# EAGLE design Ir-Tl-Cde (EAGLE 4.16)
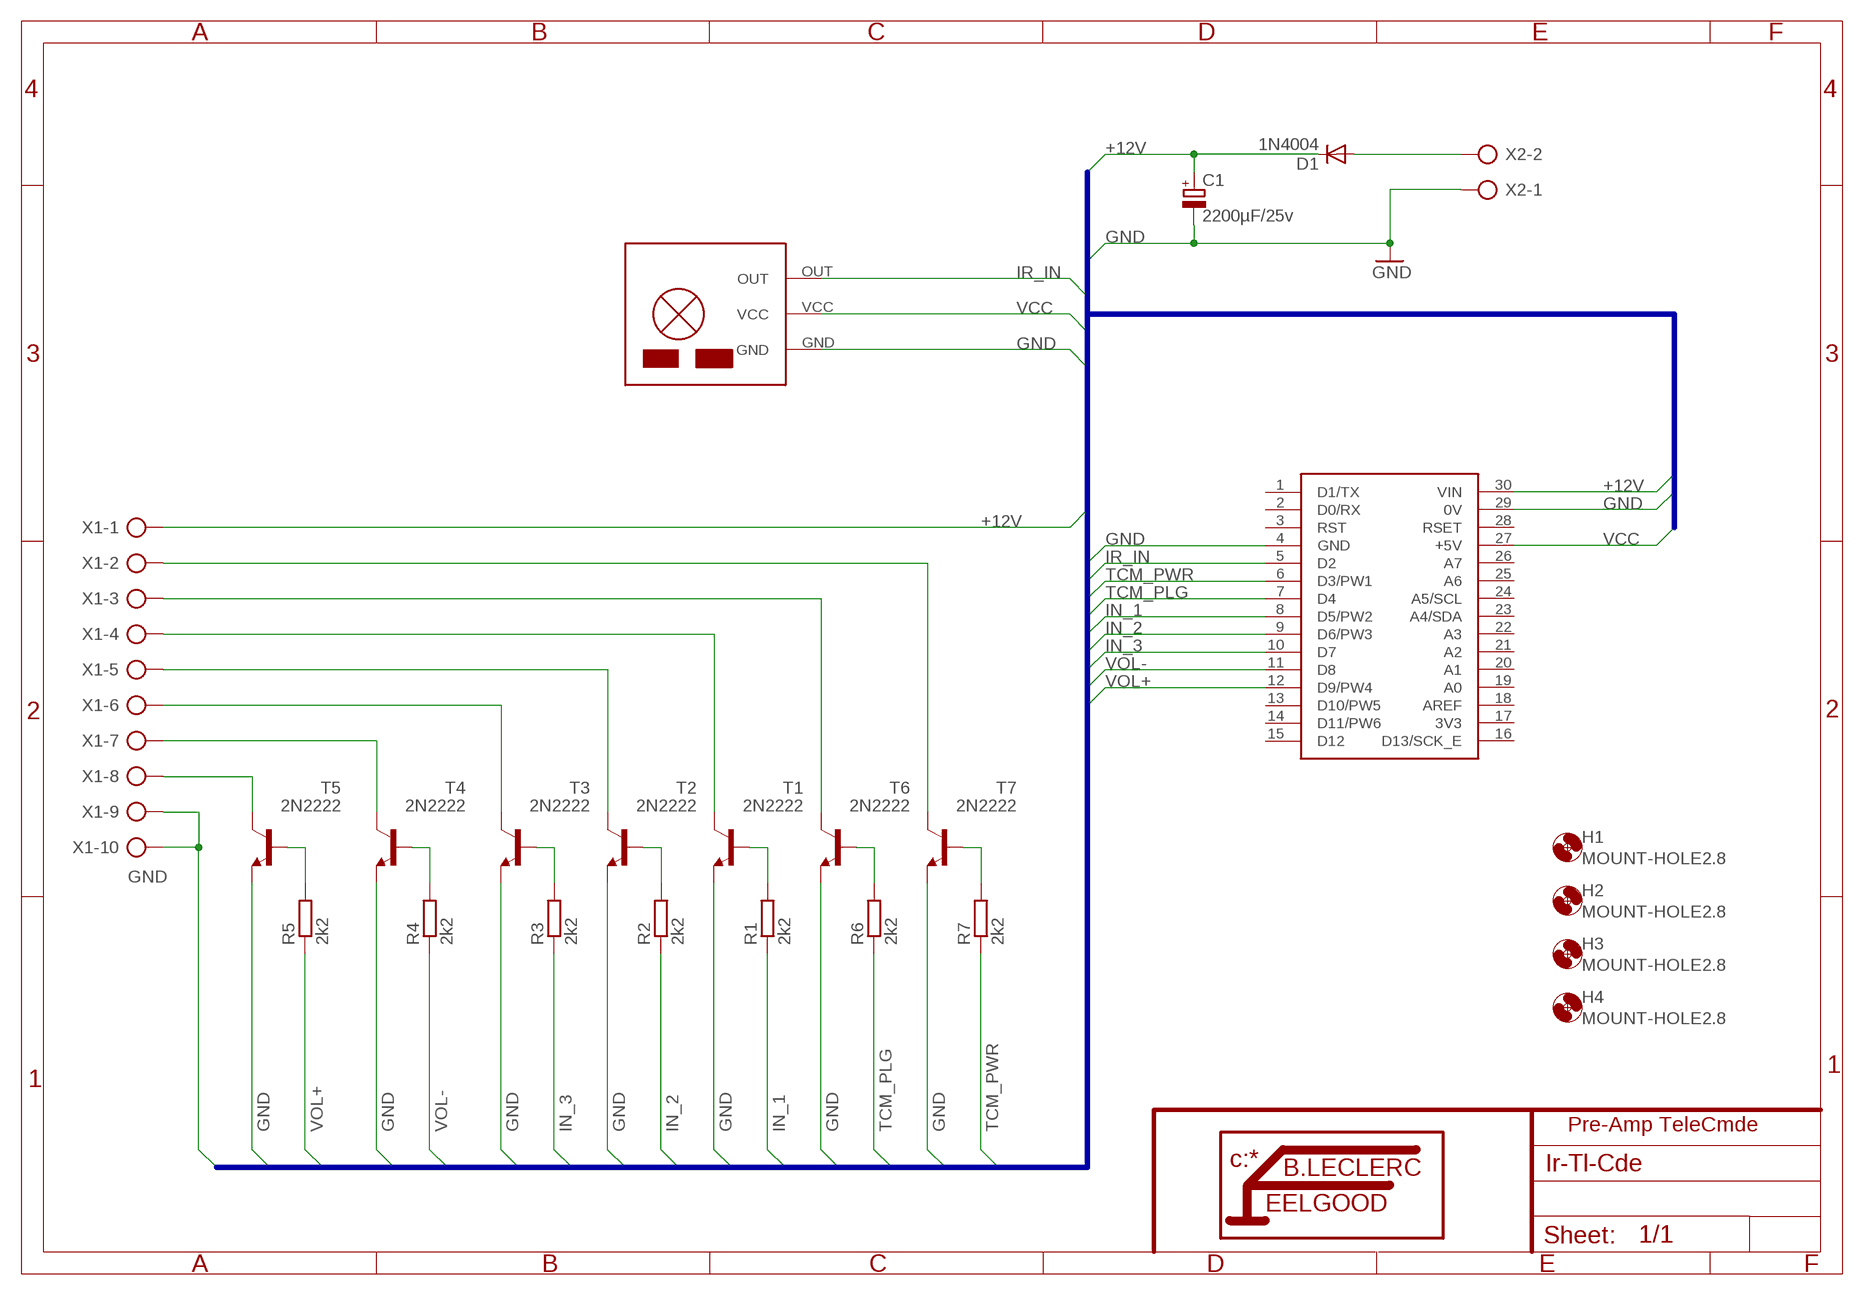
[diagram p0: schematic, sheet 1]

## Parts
C1  2200µF/25v  CPOL-EUE7.5-16  [E7,5-16]
D1  1N4004  [DO41-10]
H1  MOUNT-HOLE2.8  [2,8]
H2  MOUNT-HOLE2.8  [2,8]
H3  MOUNT-HOLE2.8  [2,8]
H4  MOUNT-HOLE2.8  [2,8]
IR1  KEYES_PCB  [KEYES_PCB]
R1  2k2  R-EU_0207/10  [0207/10]
R2  2k2  R-EU_0207/10  [0207/10]
R3  2k2  R-EU_0207/10  [0207/10]
R4  2k2  R-EU_0207/10  [0207/10]
R5  2k2  R-EU_0207/10  [0207/10]
R6  2k2  R-EU_0207/10  [0207/10]
R7  2k2  R-EU_0207/10  [0207/10]
T1  2N2222  [TO18]
T2  2N2222  [TO18]
T3  2N2222  [TO18]
T4  2N2222  [TO18]
T5  2N2222  [TO18]
T6  2N2222  [TO18]
T7  2N2222  [TO18]
U1  NANO  [NANO]
X1  AK300/10  [AK300/10]
X2  AK300/2  [AK300/2]

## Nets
+12V: C1.+ D1.C U1.30(VIN) X1.1
GND: C1.- IR1.GND T1.1(E) T2.1(E) T3.1(E) T4.1(E) T5.1(E) T6.1(E) T7.1(E) U1.4(GND) U1.29(0V) X1.9 X1.10 X2.1
IN_1: R1.1 U1.8(D5/PW2)
IN_2: R2.1 U1.9(D6/PW3)
IN_3: R3.1 U1.10(D7)
IR_IN: IR1.OUT U1.5(D2)
N$1: T5.3(C) X1.8
N$2: T4.3(C) X1.7
N$3: T3.3(C) X1.6
N$4: T2.3(C) X1.5
N$5: T1.3(C) X1.4
N$6: R5.2 T5.2(B)
N$7: R4.2 T4.2(B)
N$8: R3.2 T3.2(B)
N$9: R2.2 T2.2(B)
N$10: R1.2 T1.2(B)
N$11: D1.A X2.2
N$40: R6.2 T6.2(B)
N$59: R7.2 T7.2(B)
N$69: T6.3(C) X1.3
N$74: T7.3(C) X1.2
TCM_PLG: R6.1 U1.7(D4)
TCM_PWR: R7.1 U1.6(D3/PW1)
VCC: IR1.VCC U1.27(+5V)
VOL+: R5.1 U1.12(D9/PW4)
VOL-: R4.1 U1.11(D8)
Unconnected: U1.1(D1/TX) U1.2(D0/RX) U1.3(RST) U1.13(D10/PW5) U1.14(D11/PW6) U1.15(D12) U1.16(D13/SCK_E) U1.18(AREF) U1.19(A0) U1.20(A1) U1.21(A2) U1.22(A3) U1.23(A4/SDA) U1.24(A5/SCL) U1.25(A6) U1.26(A7) U1.28(RSET)

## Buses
B$1

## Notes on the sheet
- Pre-Amp TeleCmde

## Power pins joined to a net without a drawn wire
3V3: U1.17(3V3)

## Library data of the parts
C1 = rcl:CPOL-EU: POLARIZED CAPACITOR, European symbol
D1 = diode:1N4004: DIODE
H1-H4 = holes:MOUNT-HOLE: MOUNTING HOLE with drill center marker
IR1 = opto-vishay:KEYES_PCB
R1-R7 = rcl:R-EU_: RESISTOR, European symbol
T1-T7 = transistor:2N2222: NPN TRANSISTOR
U1 = Arduino:NANO
X1 = con-ptr500:AK300/10: CONNECTOR
X2 = con-ptr500:AK300/2: CONNECTOR

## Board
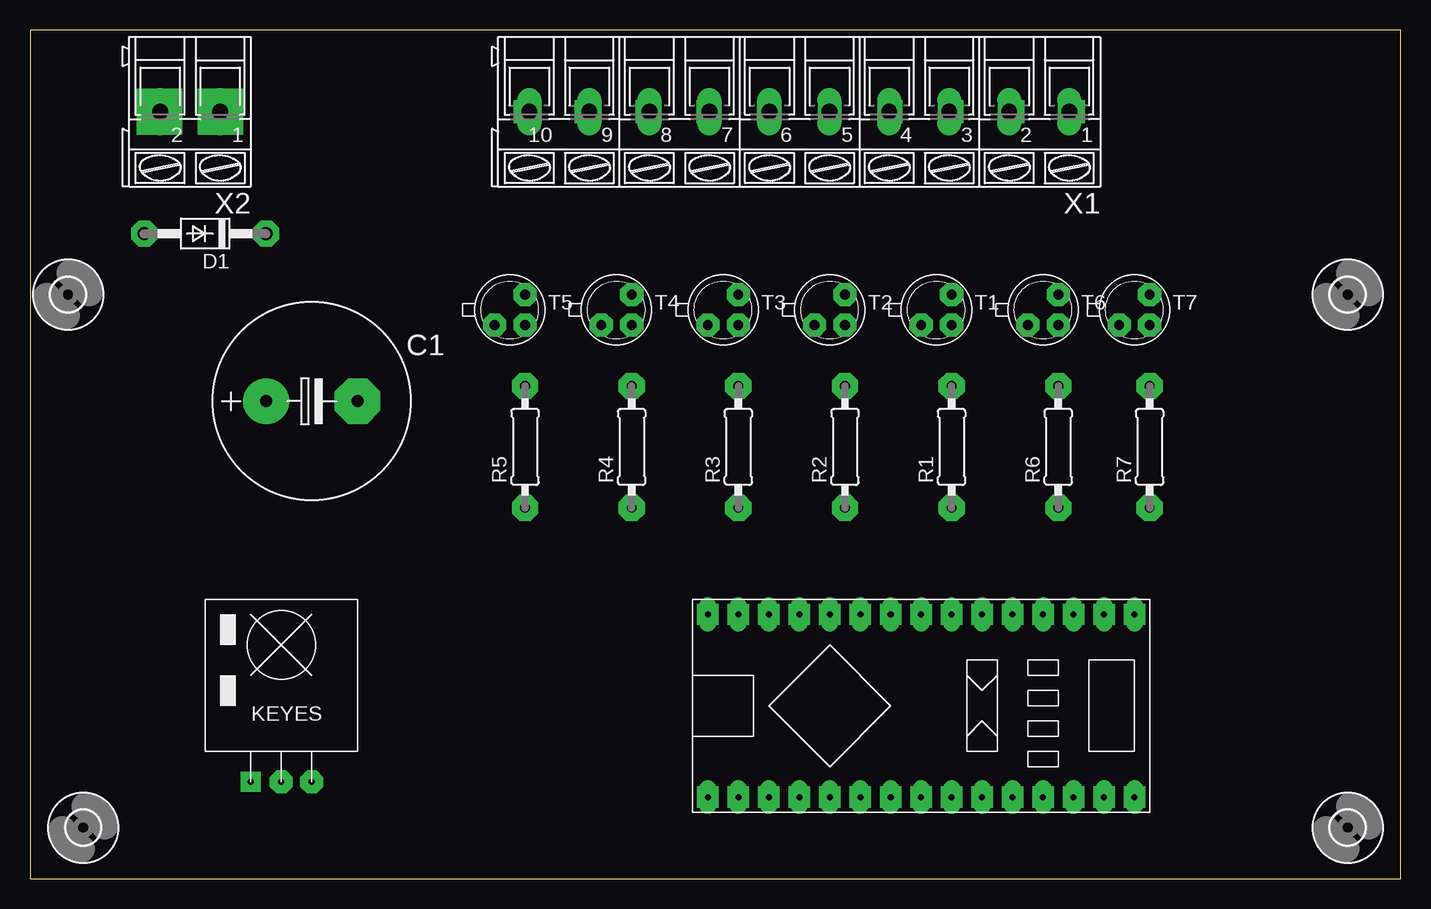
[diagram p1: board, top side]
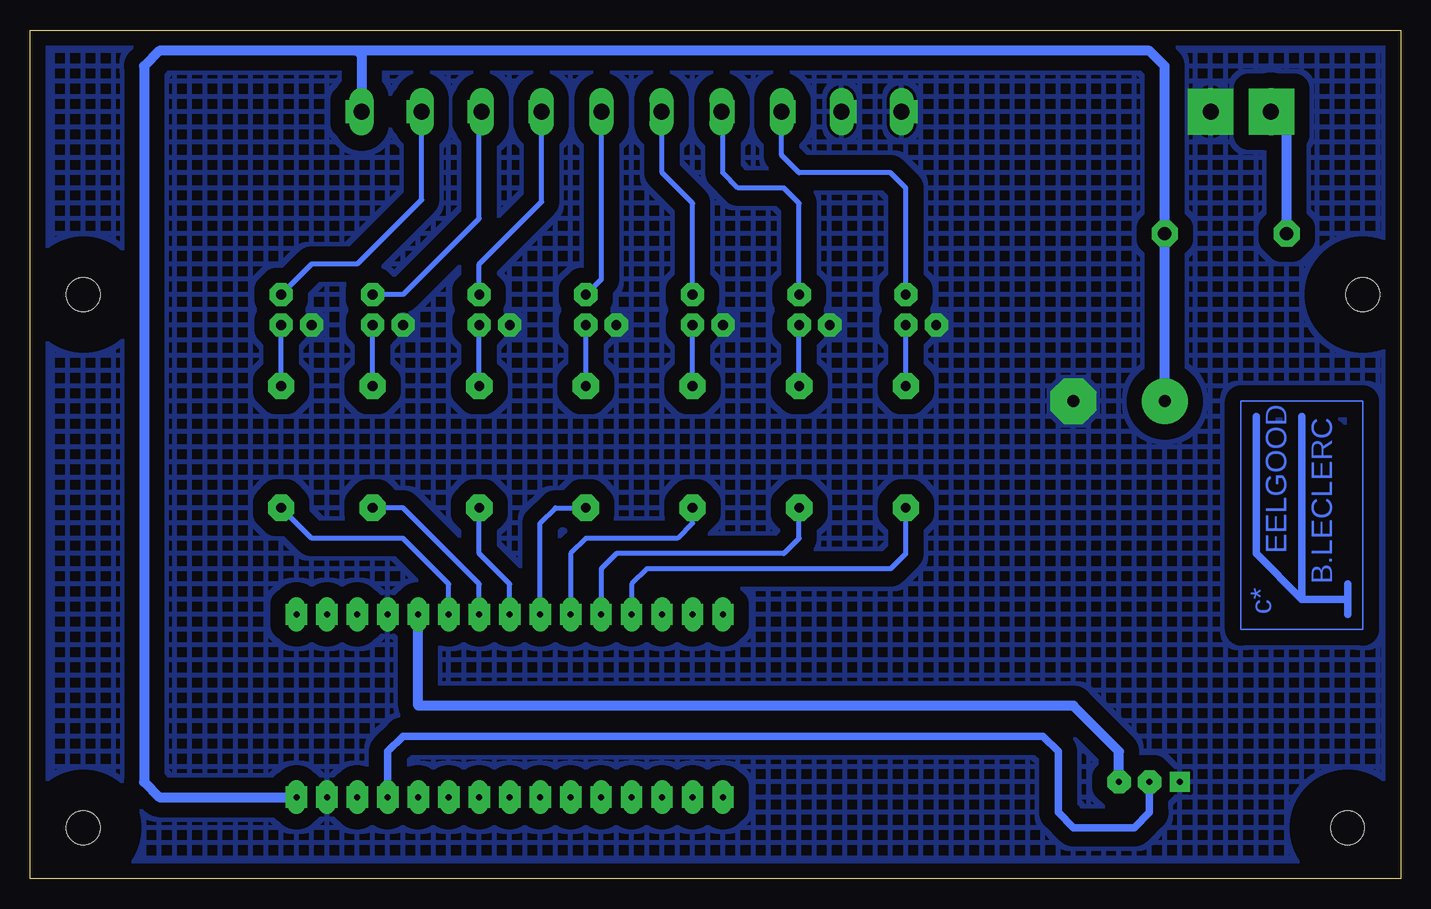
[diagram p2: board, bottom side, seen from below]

Size 114.28 x 70.79 mm. Coordinates in mm from the lower left corner, seen from the top.
Outline: 0,0 114.28,0 114.28,70.79 0,70.79 0,0
Copper layers (1*16): Top 0.035mm / dielectric 1.5mm / Bottom 0.035mm
Design rules "default": minimum track width 10mil, minimum drill 24mil, track to track 8mil, track to pad 8mil, pad to pad 8mil, via to via 8mil, smd to smd 8mil, copper to edge 40mil, drill to drill 8mil, minimum pad ring 10mil, minimum via ring 8mil, stop-mask expansion 4mil, vias tented up to drill 0mil, thermal gap 10mil

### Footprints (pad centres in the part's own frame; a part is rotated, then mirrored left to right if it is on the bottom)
E7,5-16 = drill 1.016 pad 3.15 round: + -3.81,0 | drill 1.016 pad 3.15 octagon: - 3.81,0
DO41-10 = drill 1.118 round: A 5.08,0; C -5.08,0
2,8 = hole 2.8: 0,0
KEYES_PCB = drill 0.5 pad 1.676 square: GND -2.54,-6.35 | drill 0.5 pad 1.676 round: OUT 2.54,-6.35; VCC 0,-6.35
0207/10 = drill 0.813 octagon: 1 -5.08,0; 2 5.08,0
TO18 = drill 0.813 octagon: 1 -1.27,-1.27; 2 1.27,-1.27; 3 1.27,1.27
NANO = drill 0.5 pad 1.422 long: 1 -7.62,17.78; 2 -7.62,15.24; 3 -7.62,12.7; 4 -7.62,10.16; 5 -7.62,7.62; 6 -7.62,5.08; 7 -7.62,2.54; 8 -7.62,0; 9 -7.62,-2.54; 10 -7.62,-5.08; 11 -7.62,-7.62; 12 -7.62,-10.16; 13 -7.62,-12.7; 14 -7.62,-15.24; 15 -7.62,-17.78; 16 7.62,-17.78; 17 7.62,-15.24; 18 7.62,-12.7; 19 7.62,-10.16; 20 7.62,-7.62; 21 7.62,-5.08; 22 7.62,-2.54; 23 7.62,0; 24 7.62,2.54; 25 7.62,5.08; 26 7.62,7.62; 27 7.62,10.16; 28 7.62,12.7; 29 7.62,15.24; 30 7.62,17.78
AK300/10 = drill 1.321 long: 1 -22.504,0; 2 -17.501,0; 3 -12.497,0; 4 -7.493,0; 5 -2.515,0; 6 2.489,0; 7 7.493,0; 8 12.497,0; 9 17.501,0; 10 22.504,0
AK300/2 = drill 1.321 long: 1 -2.515,0; 2 2.489,0

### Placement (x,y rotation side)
C1  23.49,39.84 0 top
D1  14.6,53.81 180 top
H1  4.44,4.28 0 top
H2  109.85,4.28 0 top
H3  3.17,48.73 0 top
H4  109.85,48.73 0 top
IR1  20.95,14.44 0 top
R1  76.83,36.03 90 top
R2  67.94,36.03 90 top
R3  59.05,36.03 90 top
R4  50.16,36.03 90 top
R5  41.27,36.03 90 top
R6  85.72,36.03 90 top
R7  93.34,36.03 90 top
T1  75.56,47.46 0 top
T2  66.67,47.46 0 top
T3  57.78,47.46 0 top
T4  48.89,47.46 0 top
T5  40,47.46 0 top
T6  84.45,47.46 0 top
T7  92.07,47.46 0 top
U1  74.29,14.44 270 top
U$2  [LITTFEEL]  0.63,23.33 90 bottom
X1  64.13,63.97 180 top
X2  13.33,63.97 180 top

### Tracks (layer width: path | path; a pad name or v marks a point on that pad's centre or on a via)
+12V
  Bottom 0.813: C1.+ D1.C 19.68,67.78 20.95,69.05 86.99,69.05 | 86.99,69.05 103.5,69.05 104.77,67.78 104.77,8.09 103.5,6.82 U1.30 | X1.1 86.63,68.69 86.99,69.05
GND  (via drill 0.5 pad 1.78, 0.5 pad 1.93, 0.5 pad 3.81)
  other vias: 15.87,63.97 27.3,39.84 38.73,46.19 47.62,46.19 56.51,46.19 65.4,46.19 74.29,46.19 41.27,63.97 46.35,63.97 84.45,22.06 89.53,6.82 83.18,46.19 90.8,46.19
  pour Bottom (isolate 1.27, hatched): 0.63,70.32 113.66,70.32 113.66,0.47 0.63,0.47
IN_1
  Bottom 0.406: U1.8 74.29,24.6 76.83,27.14 R1.1
IN_2
  Bottom 0.406: U1.9 71.75,29.68 70.48,30.95 R2.1
IN_3
  Bottom 0.406: U1.10 69.21,27.14 67.94,28.41 60.32,28.41 59.05,29.68 R3.1
IR_IN
  Bottom 0.813: U1.5 81.91,14.44 27.3,14.44 23.49,10.63 IR1.OUT
N$1
  Bottom 0.406: T5.3 41.27,57.62 42.54,58.89 50.16,58.89 51.63,60.36 X1.8
N$2  (via drill 0.5 pad 1.93)
  Bottom 0.406: T4.3 50.16,56.35 51.43,57.62 55.24,57.62 56.51,58.89 v56.51,63.97 X1.7
N$3  (via drill 0.5 pad 1.93)
  Bottom 0.406: T3.3 59.05,56.35 61.59,58.89 v61.59,63.97 X1.6
N$4
  Bottom 0.406: X1.5 66.64,50.02 T2.3
N$5
  Bottom 0.406: X1.4 71.62,56.48 76.83,51.27 T1.3
N$6
  Bottom 0.406: R5.2 T5.2
N$7
  Bottom 0.406: R4.2 T4.2
N$8
  Bottom 0.406: R3.2 T3.2
N$9
  Bottom 0.406: R2.2 T2.2
N$10
  Bottom 0.406: R1.2 T1.2
N$11  (via drill 0.5 pad 3.81)
  Bottom 0.813: D1.A 9.52,63.97 v10.79,63.97 X2.2
N$12  (via drill 0.5 pad 1.93)
  other vias: 20.95,8.09
N$13  (via drill 0.5 pad 3.81)
  other vias: 19.68,39.84
N$14  (via drill 0.5 pad 1.93)
  other vias: 86.99,63.97
N$15  (via drill 0.5 pad 1.93)
  other vias: 81.91,63.97
N$16  (via drill 0.5 pad 1.93)
  other vias: 76.83,63.97
N$17  (via drill 0.5 pad 2.18)
  other vias: 9.52,53.81
N$18  (via drill 0.5 pad 2.18)
  other vias: 19.68,53.81
N$19  (via drill 0.5 pad 1.93)
  other vias: 71.75,63.97
N$20  (via drill 0.5 pad 1.93)
  other vias: 76.83,48.73
N$21  (via drill 0.5 pad 1.93)
  other vias: 76.83,46.19
N$22  (via drill 0.5 pad 1.93)
  other vias: 66.67,63.97
N$23  (via drill 0.5 pad 1.93)
  other vias: 67.94,48.73
N$24  (via drill 0.5 pad 2.18)
  other vias: 76.83,41.11
N$25  (via drill 0.5 pad 1.93)
  other vias: 67.94,46.19
N$26  (via drill 0.5 pad 1.93)
  other vias: 59.05,48.73
N$27  (via drill 0.5 pad 2.18)
  other vias: 76.83,30.95
N$28  (via drill 0.5 pad 2.18)
  other vias: 59.05,41.11
N$29  (via drill 0.5 pad 2.18)
  other vias: 67.94,30.95
N$30  (via drill 0.5 pad 2.18)
  other vias: 59.05,30.95
N$31  (via drill 0.5 pad 2.18)
  other vias: 41.27,41.11
N$32  (via drill 0.5 pad 2.18)
  other vias: 50.16,30.95
N$33  (via drill 0.5 pad 2.18)
  other vias: 41.27,30.95
N$34  (via drill 0.5 pad 2.18)
  other vias: 50.16,41.11
N$35  (via drill 0.5 pad 2.18)
  other vias: 67.94,41.11
N$36  (via drill 0.5 pad 1.93)
  other vias: 51.43,63.97
N$37  (via drill 0.5 pad 1.93)
  other vias: 59.05,46.19
N$38  (via drill 0.5 pad 1.78)
  other vias: 71.75,6.82
N$39  (via drill 0.5 pad 1.93)
  other vias: 50.16,48.73
N$40
  Bottom 0.406: R6.2 T6.2
N$41  (via drill 0.5 pad 1.93)
  other vias: 41.27,48.73
N$42  (via drill 0.5 pad 1.93)
  other vias: 50.16,46.19
N$43  (via drill 0.5 pad 1.93)
  other vias: 41.27,46.19
N$44  (via drill 0.5 pad 1.78)
  other vias: 89.53,22.06
N$45  (via drill 0.5 pad 1.93)
  other vias: 23.49,8.09
N$46  (via drill 0.5 pad 1.78)
  other vias: 81.91,22.06
N$47  (via drill 0.5 pad 1.78)
  other vias: 71.75,22.06
N$48  (via drill 0.5 pad 1.78)
  other vias: 69.21,22.06
N$49  (via drill 0.5 pad 1.78)
  other vias: 74.29,22.06
N$50  (via drill 0.5 pad 1.78)
  other vias: 92.07,22.06
N$51  (via drill 0.5 pad 1.78)
  other vias: 81.91,6.82
N$52  (via drill 0.5 pad 1.78)
  other vias: 74.29,6.82
N$53  (via drill 0.5 pad 1.78)
  other vias: 69.21,6.82
N$54  (via drill 0.5 pad 1.78)
  other vias: 64.13,6.82
N$55  (via drill 0.5 pad 1.78)
  other vias: 66.67,6.82
N$56  (via drill 0.5 pad 1.78)
  other vias: 86.99,6.82
N$57  (via drill 0.5 pad 1.78)
  other vias: 92.07,6.82
N$58  (via drill 0.5 pad 1.78)
  other vias: 86.99,22.06
N$59
  Bottom 0.406: R7.2 T7.2
N$60  (via drill 0.5 pad 1.78)
  other vias: 66.67,22.06
N$61  (via drill 0.5 pad 1.78)
  other vias: 64.13,22.06
N$62  (via drill 0.5 pad 1.78)
  other vias: 59.05,22.06
N$63  (via drill 0.5 pad 1.78)
  other vias: 61.59,22.06
N$64  (via drill 0.5 pad 1.78)
  other vias: 76.83,22.06
N$65  (via drill 0.5 pad 1.78)
  other vias: 79.37,22.06
N$66  (via drill 0.5 pad 1.78)
  other vias: 84.45,6.82
N$67  (via drill 0.5 pad 1.78)
  other vias: 79.37,6.82
N$68  (via drill 0.5 pad 1.78)
  other vias: 76.83,6.82
N$69
  Bottom 0.406: X1.3 76.83,63.97 76.83,55.08 83.18,48.73 T6.3
N$70  (via drill 0.5 pad 1.78)
  other vias: 56.51,6.82
N$71  (via drill 0.5 pad 1.78)
  other vias: 59.05,6.82
N$72  (via drill 0.5 pad 1.78)
  other vias: 61.59,6.82
N$73  (via drill 0.5 pad 1.78)
  other vias: 56.51,22.06
N$74
  Bottom 0.406: X1.2 81.63,56.63 86.99,51.27 90.8,51.27 T7.3
N$75  (via drill 0.5 pad 2.18)
  other vias: 93.34,41.11
N$76  (via drill 0.5 pad 2.18)
  other vias: 85.72,41.11
N$77  (via drill 0.5 pad 2.18)
  other vias: 85.72,30.95
N$78  (via drill 0.5 pad 2.18)
  other vias: 93.34,30.95
N$81  (via drill 0.5 pad 1.93)
  other vias: 93.34,46.19
N$82  (via drill 0.5 pad 1.93)
  other vias: 85.72,46.19
N$83  (via drill 0.5 pad 1.93)
  other vias: 93.34,48.73
N$84  (via drill 0.5 pad 1.93)
  other vias: 85.72,48.73
TCM_PLG
  Bottom 0.406: U1.7 76.83,24.6 83.18,30.95 R6.1
TCM_PWR
  Bottom 0.406: U1.6 79.37,24.6 83.18,28.41 90.8,28.41 R7.1
VCC
  Bottom 0.61: IR1.VCC 20.95,5.55 22.22,4.28 27.3,4.28 28.57,5.55 28.57,10.63 29.84,11.9 83.18,11.9 84.45,10.63 U1.27
VOL+
  Bottom 0.406: U1.12 64.13,24.6 62.86,25.87 42.54,25.87 41.27,27.14 R5.1
VOL-
  Bottom 0.406: U1.11 66.67,25.87 65.4,27.14 51.43,27.14 50.16,28.41 R4.1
